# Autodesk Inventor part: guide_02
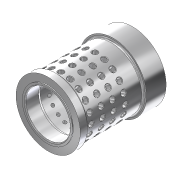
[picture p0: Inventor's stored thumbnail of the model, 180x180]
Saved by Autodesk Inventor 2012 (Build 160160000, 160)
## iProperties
Created: 2002-03
Part Number: guide_02
Document SubType Name: Modeling
Designer: Lieven Grauls
Stock Number: guide_02
Project: Valve Techcamp 2008
Density: 1 g/cm^3
Mass: 121.014 g
Surface Area: 393.413 cm^2
Volume: 121.014 cm^3
Material: Default
Company: Autodesk
Control State: 0
Master: False
Checked Out: False
Shininess: 59.0
Length Units: 11269
Angle Units: 11279
Time Units: 11290
Mass Units: 11283
Length Display Precision: 3
Angle Display Precision: 2
Density: 0.0
Volumn: 0.0
Area: 0.0
PropertySet Name: Model Information
Author: Lieven Grauls
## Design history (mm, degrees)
sketch "Sketch1"
  geometry: L1 (0, 113.1)-(0, -18.85) reference; L2 (22, 0)-(39.5, 0) reference; L3 (24.5, 0)-(24.5, 14.855); L4 (24.5, 14.855)-(26.5, 18.25); L5 (26.5, 18.25)-(26.5, 94.25); L6 (26.5, 94.25)-(37, 94.25); L7 (37, 94.25)-(37, 72.612); L8 (37, 72.612)-(33.467, 72.612); L9 (35.468, 0.9)-(27.75, 0.9); L10 (27.75, 0.9)-(27.75, 0); L11 (35.468, 8.821)-(33.468, 8.821); L12 (33.468, 8.821)-(33.467, 72.612); L13 (35.468, 8.821)-(35.468, 0.9)
  constraints: 22 end point, 8 perpendicular, 2 parallel, 2 point on line
  dimensions: "d3" = 0.9 distance from line of L10.end L9; "d6" = 21.638 distance of L7.end L6.end; "d11" = 30.5 deg angle of L5 L4; "d12" = 76 vertical distance of L4.end L6.end; "d83" = 53 diameter of L5.end L1; "d85" = 74 diameter of L6.end L1; "d86" = 49 diameter of L3 L1; "d87" = 55.5 diameter of L10.end L1; "d97" = 93.35 distance between parallel lines of L6 L9; "d99" = 2 distance of L11.start L11.end; "d100" = 70.935 diameter of L13 L1; "d101" = 7.921 distance of L11.start L9.start
revolve "Revolution1" sketch "Sketch1" stored, may be unused: angle "d13" = 90 deg
workplane "Work Plane1"
sketch "Sketch2"
  geometry: L1 (0, 29.669)-(0, -102.281) reference; L2 (-27.75, -83.431)-(27.75, -83.431) reference; 4 further points
  constraints: 4 point on line
  dimensions: "d21" = 24 distance from line of point (0, -59.431) L2; "d104" = 10 distance of point (0, -49.431) point (0, -59.431); "d105" = 10 distance of point (0, -39.431) point (0, -49.431) (= d104); "d106" = 10 distance of point (0, -29.431) point (0, -39.431) (= d104)
hole "Hole1" sketch "Sketch2" diameter "d28" = 5.5; stored, may be unused: countersink angle "d32" = 82 deg, drill point angle "d34" = 118 deg; dims "d29" = 6, "d30" = 4, "d31" = 2, "d33" = 20
fillet "Fillet4" dims "d103" = 0.5
fillet "Fillet2" dims "d98" = 2
fillet "Fillet3" dims "d102" = 1
node "Volumenkörper1"
node "Volumenkörpern"
node "Oberflächenkörpern"
pattern_circular "Circular Pattern2" dims angle "d54" = 360 deg
